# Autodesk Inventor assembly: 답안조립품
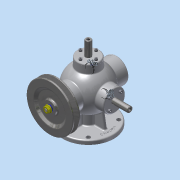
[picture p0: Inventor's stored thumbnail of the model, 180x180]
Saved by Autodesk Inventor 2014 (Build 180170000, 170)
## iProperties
Created: 2016-01
Part Number: 답안조립품
Document SubType Name: Assembly
Designer: Administrator
Mass: 3734.97 g
Surface Area: 2410.99 cm^2
Volume: 903.657 cm^3
Density: 4.13317 g/cm^3
Author: Administrator
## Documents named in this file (17)
- C:\Users\Administrator\Desktop\360108V1015\답안조립품.iam
- C:\Users\Administrator\Desktop\360108V1015\본체.ipt
- C:\Users\Administrator\Desktop\360108V1015\15-스프링.ipt
- C:\Users\Administrator\Desktop\360108V1015\16-스프링.ipt
- C:\Users\Administrator\Desktop\360108V1015\V-벨트풀리.ipt
- C:\Users\Administrator\Desktop\360108V1015\너트-M8x1.ipt
- C:\Users\Administrator\Desktop\360108V1015\뒤커버.ipt
- C:\Users\Administrator\Desktop\360108V1015\베어링- 6202.ipt
- C:\Users\Administrator\Desktop\360108V1015\본체커버.ipt
- C:\Users\Administrator\Desktop\360108V1015\볼트 M4x0.7.ipt
- C:\Users\Administrator\Desktop\360108V1015\슬라이드 커버.ipt
- C:\Users\Administrator\Desktop\360108V1015\슬라이드.ipt
- C:\Users\Administrator\Desktop\360108V1015\앞커버.ipt
- C:\Users\Administrator\Desktop\360108V1015\오일실.ipt
- C:\Users\Administrator\Desktop\360108V1015\와셔 8x17.ipt
- C:\Users\Administrator\Desktop\360108V1015\축.ipt
- C:\Users\Administrator\Desktop\360108V1015\키-4x4.ipt
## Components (20 placed, 4 different names)
1. 15-스프링:1
2. 16-스프링:1
3. V-벨트풀리:1 — 플러쉬:1, 플러쉬:2, 각도:2, 각도:3
4. M4x0.7x12:3
5. M4x0.7x12:4
6. M4x0.7x12:5
7. M4x0.7x12:6
8. M4x0.7x12:7
9. M4x0.7x12:8
10. M4x0.7x12:9
11. M4x0.7x12:10
12. M4x0.7x12:11
13. M4x0.7x12:1
14. M4x0.7x12:12
15. M4x0.7x12:13
16. M4x0.7x12:14
17. M4x0.7x12:2
18. M4x0.7x12:15
19. M4x0.7x12:16
20. M4x0.7x12:17
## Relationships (4: Flush 2, Angle 2)
- 플러쉬:1 [Flush]: V-벨트풀리:1
- 플러쉬:2 [Flush]: V-벨트풀리:1
- 각도:2 [Angle]: V-벨트풀리:1
- 각도:3 [Angle]: V-벨트풀리:1
